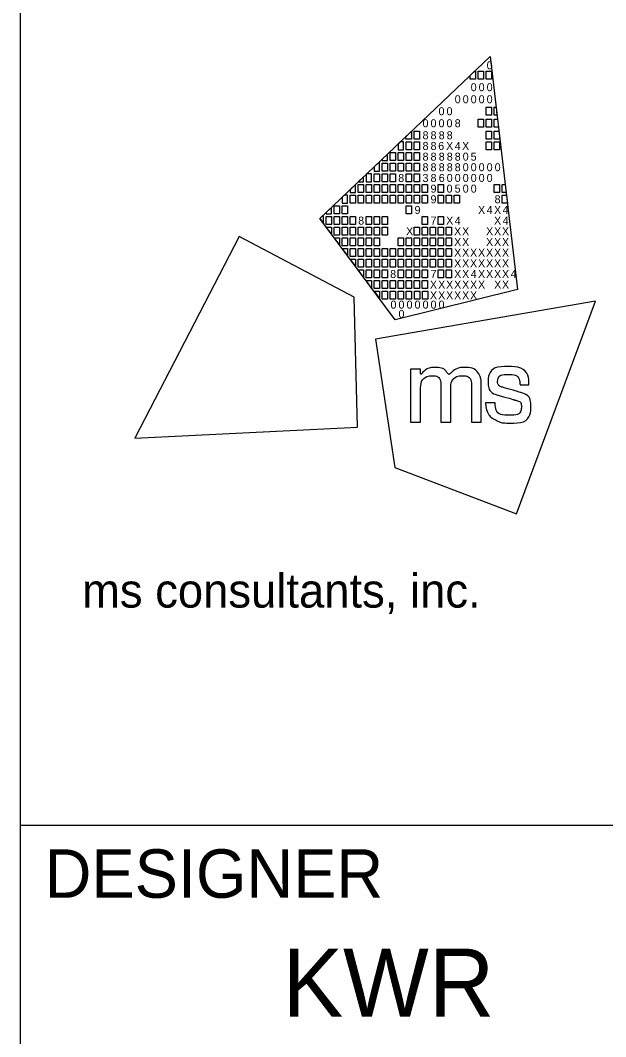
# Model space of a CAD drawing. Extents: x 0 to 34, y 0 to 22.
# Drawn here: x 32 to 33.207, y 2.063 to 4.161 of the extents above; entities that cross this region are included whole.
import ezdxf

# ---------------------------------------------------------------- set-up
doc = ezdxf.new("R2010")
doc.units = 0
doc.layers.add('SH_Border', color=7, linetype='Continuous')
doc.layers.add('SH_Data', color=7, linetype='Continuous')

msp = doc.modelspace()

# ---------------------------------------------------------------- linework, layer by layer
at = {"layer": 'SH_Border'}
for p, q in [((32, 0.5), (32, 21.5)), ((32, 2.5), (33.5, 2.5))]:
    msp.add_line(p, q, dxfattribs=at)
at = {"layer": 'SH_Data'}
for p, q in [((32.6175, 3.7519), (32.9688, 4.0861)), ((32.9688, 4.0861), (32.9688, 4.0861)), ((32.9688, 4.0861), (33.0253, 3.6052)), ((32.773, 3.543), (32.6175, 3.7519)), ((33.0253, 3.6052), (32.773, 3.543)), ((32.75, 3.5), (32.75, 3.5))]:
    msp.add_line(p, q, dxfattribs=at)
for points in [[(32.9279, 4.0472), (32.9369, 4.0558), (32.9389, 4.0558), (32.9389, 4.0393), (32.9279, 4.0393)], [(32.9444, 4.0558), (32.9554, 4.0558), (32.9554, 4.0393), (32.9444, 4.0393)], [(32.9609, 4.0558), (32.9719, 4.0558), (32.9719, 4.0393), (32.9609, 4.0393)], [(32.9606, 3.9815), (32.9716, 3.9815), (32.9716, 3.965), (32.9606, 3.965)], [(32.9771, 3.9815), (32.9811, 3.9815), (32.983, 3.965), (32.9771, 3.965)], [(32.9441, 3.9567), (32.9551, 3.9567), (32.9551, 3.9402), (32.9441, 3.9402)], [(32.9606, 3.9567), (32.9716, 3.9567), (32.9716, 3.9402), (32.9606, 3.9402)], [(32.9771, 3.9567), (32.984, 3.9567), (32.9859, 3.9402), (32.9771, 3.9402)], [(32.7953, 3.9211), (32.8064, 3.9316), (32.8064, 3.9154), (32.7953, 3.9154)], [(32.8123, 3.9319), (32.8233, 3.9319), (32.8233, 3.9154), (32.8123, 3.9154)], [(32.9606, 3.9319), (32.9716, 3.9319), (32.9716, 3.9154), (32.9606, 3.9154)], [(32.9771, 3.9319), (32.9869, 3.9319), (32.9881, 3.9218), (32.9881, 3.9154), (32.9771, 3.9154)], [(32.7958, 3.9099), (32.8068, 3.9099), (32.8068, 3.8934), (32.7958, 3.8934)], [(32.8123, 3.9099), (32.8233, 3.9099), (32.8233, 3.8934), (32.8123, 3.8934)], [(32.9606, 3.9099), (32.9716, 3.9099), (32.9716, 3.8934), (32.9606, 3.8934)], [(32.9771, 3.9099), (32.9881, 3.9099), (32.9881, 3.8934), (32.9771, 3.8934)], [(32.7627, 3.8879), (32.7737, 3.8879), (32.7737, 3.8714), (32.7627, 3.8714)], [(32.7793, 3.8879), (32.7903, 3.8879), (32.7903, 3.8714), (32.7793, 3.8714)], [(32.7958, 3.8879), (32.8068, 3.8879), (32.8068, 3.8714), (32.7958, 3.8714)], [(32.8123, 3.8879), (32.8233, 3.8879), (32.8233, 3.8714), (32.8123, 3.8714)], [(32.7462, 3.8659), (32.7572, 3.8659), (32.7572, 3.8494), (32.7462, 3.8494)], [(32.7627, 3.8659), (32.7737, 3.8659), (32.7737, 3.8494), (32.7627, 3.8494)], [(32.7793, 3.8659), (32.7903, 3.8659), (32.7903, 3.8494), (32.7793, 3.8494)], [(32.7958, 3.8659), (32.8068, 3.8659), (32.8068, 3.8494), (32.7958, 3.8494)], [(32.8123, 3.8659), (32.8233, 3.8659), (32.8233, 3.8494), (32.8123, 3.8494)], [(32.7297, 3.8439), (32.7407, 3.8439), (32.7407, 3.8273), (32.7297, 3.8273)], [(32.7462, 3.8439), (32.7572, 3.8439), (32.7572, 3.8273), (32.7462, 3.8273)], [(32.7627, 3.8439), (32.7737, 3.8439), (32.7737, 3.8273), (32.7627, 3.8273)], [(32.7958, 3.8439), (32.8068, 3.8439), (32.8068, 3.8273), (32.7958, 3.8273)], [(32.8123, 3.8439), (32.8233, 3.8439), (32.8233, 3.8273), (32.8123, 3.8273)], [(32.6967, 3.8218), (32.7077, 3.8218), (32.7077, 3.8053), (32.6967, 3.8053)], [(32.7132, 3.8218), (32.7242, 3.8218), (32.7242, 3.8053), (32.7132, 3.8053)], [(32.7297, 3.8218), (32.7407, 3.8218), (32.7407, 3.8053), (32.7297, 3.8053)], [(32.7462, 3.8218), (32.7572, 3.8218), (32.7572, 3.8053), (32.7462, 3.8053)], [(32.7627, 3.8218), (32.7737, 3.8218), (32.7737, 3.8053), (32.7627, 3.8053)], [(32.7793, 3.8218), (32.7903, 3.8218), (32.7903, 3.8053), (32.7793, 3.8053)], [(32.7958, 3.8218), (32.8068, 3.8218), (32.8068, 3.8053), (32.7958, 3.8053)], [(32.8123, 3.8218), (32.8233, 3.8218), (32.8233, 3.8053), (32.8123, 3.8053)], [(32.8288, 3.8218), (32.8398, 3.8218), (32.8398, 3.8053), (32.8288, 3.8053)], [(32.8618, 3.8218), (32.8728, 3.8218), (32.8728, 3.8053), (32.8618, 3.8053)], [(32.9771, 3.8218), (32.9881, 3.8218), (32.9881, 3.8053), (32.9771, 3.8053)], [(32.9935, 3.8218), (32.9998, 3.8218), (33.0018, 3.8053), (32.9935, 3.8053)], [(32.6802, 3.7998), (32.6912, 3.7998), (32.6912, 3.7833), (32.6802, 3.7833)], [(32.6967, 3.7998), (32.7077, 3.7998), (32.7077, 3.7833), (32.6967, 3.7833)], [(32.7132, 3.7998), (32.7242, 3.7998), (32.7242, 3.7833), (32.7132, 3.7833)], [(32.7297, 3.7998), (32.7407, 3.7998), (32.7407, 3.7833), (32.7297, 3.7833)], [(32.7462, 3.7998), (32.7572, 3.7998), (32.7572, 3.7833), (32.7462, 3.7833)], [(32.7627, 3.7998), (32.7737, 3.7998), (32.7737, 3.7833), (32.7627, 3.7833)], [(32.7793, 3.7998), (32.7903, 3.7998), (32.7903, 3.7833), (32.7793, 3.7833)], [(32.7958, 3.7998), (32.8068, 3.7998), (32.8068, 3.7833), (32.7958, 3.7833)], [(32.8123, 3.7998), (32.8233, 3.7998), (32.8233, 3.7833), (32.8123, 3.7833)], [(32.8288, 3.7998), (32.8398, 3.7998), (32.8398, 3.7833), (32.8288, 3.7833)], [(32.8618, 3.7998), (32.8728, 3.7998), (32.8728, 3.7833), (32.8618, 3.7833)], [(32.8783, 3.7998), (32.8893, 3.7998), (32.8893, 3.7833), (32.8783, 3.7833)], [(32.8947, 3.7998), (32.9057, 3.7998), (32.9057, 3.7833), (32.8947, 3.7833)], [(32.9935, 3.7998), (33.0024, 3.7998), (33.0044, 3.7833), (32.9935, 3.7833)], [(32.6471, 3.7778), (32.6581, 3.7778), (32.6581, 3.7613), (32.6471, 3.7613)], [(32.6637, 3.7778), (32.6747, 3.7778), (32.6747, 3.7613), (32.6637, 3.7613)], [(32.7958, 3.7778), (32.8068, 3.7778), (32.8068, 3.7613), (32.7958, 3.7613)], [(32.6306, 3.7558), (32.6416, 3.7558), (32.6416, 3.7393), (32.6306, 3.7393)], [(32.6471, 3.7558), (32.6581, 3.7558), (32.6581, 3.7393), (32.6471, 3.7393)], [(32.6637, 3.7558), (32.6747, 3.7558), (32.6747, 3.7393), (32.6637, 3.7393)], [(32.6802, 3.7558), (32.6912, 3.7558), (32.6912, 3.7393), (32.6802, 3.7393)], [(32.7132, 3.7558), (32.7242, 3.7558), (32.7242, 3.7393), (32.7132, 3.7393)], [(32.7297, 3.7558), (32.7407, 3.7558), (32.7407, 3.7393), (32.7297, 3.7393)], [(32.7462, 3.7558), (32.7572, 3.7558), (32.7572, 3.7393), (32.7462, 3.7393)], [(32.8288, 3.7558), (32.8398, 3.7558), (32.8398, 3.7393), (32.8288, 3.7393)], [(32.8618, 3.7558), (32.8728, 3.7558), (32.8728, 3.7393), (32.8618, 3.7393)], [(32.6306, 3.7338), (32.6416, 3.7338), (32.6416, 3.72)], [(32.6471, 3.7338), (32.6581, 3.7338), (32.6581, 3.7173), (32.6471, 3.7173)], [(32.6637, 3.7338), (32.6747, 3.7338), (32.6747, 3.7173), (32.6637, 3.7173)], [(32.6802, 3.7338), (32.6912, 3.7338), (32.6912, 3.7173), (32.6802, 3.7173)], [(32.6967, 3.7338), (32.7077, 3.7338), (32.7077, 3.7173), (32.6967, 3.7173)], [(32.7132, 3.7338), (32.7242, 3.7338), (32.7242, 3.7173), (32.7132, 3.7173)], [(32.7297, 3.7338), (32.7407, 3.7338), (32.7407, 3.7173), (32.7297, 3.7173)], [(32.7462, 3.7338), (32.7572, 3.7338), (32.7572, 3.7173), (32.7462, 3.7173)], [(32.8123, 3.7338), (32.8233, 3.7338), (32.8233, 3.7173), (32.8123, 3.7173)], [(32.8288, 3.7338), (32.8398, 3.7338), (32.8398, 3.7173), (32.8288, 3.7173)], [(32.8453, 3.7338), (32.8563, 3.7338), (32.8563, 3.7173), (32.8453, 3.7173)], [(32.8618, 3.7338), (32.8728, 3.7338), (32.8728, 3.7173), (32.8618, 3.7173)], [(32.8783, 3.7338), (32.8893, 3.7338), (32.8893, 3.7173), (32.8783, 3.7173)], [(32.6471, 3.7117), (32.6581, 3.7117), (32.6581, 3.698)], [(32.6637, 3.7117), (32.6747, 3.7117), (32.6747, 3.6952), (32.6637, 3.6952)], [(32.6802, 3.7117), (32.6912, 3.7117), (32.6912, 3.6952), (32.6802, 3.6952)], [(32.6967, 3.7117), (32.7077, 3.7117), (32.7077, 3.6952), (32.6967, 3.6952)], [(32.7132, 3.7117), (32.7242, 3.7117), (32.7242, 3.6952), (32.7132, 3.6952)], [(32.7297, 3.7117), (32.7407, 3.7117), (32.7407, 3.6952), (32.7297, 3.6952)], [(32.7793, 3.7117), (32.7903, 3.7117), (32.7903, 3.6952), (32.7793, 3.6952)], [(32.7958, 3.7117), (32.8068, 3.7117), (32.8068, 3.6952), (32.7958, 3.6952)], [(32.8123, 3.7117), (32.8233, 3.7117), (32.8233, 3.6952), (32.8123, 3.6952)], [(32.8288, 3.7117), (32.8398, 3.7117), (32.8398, 3.6952), (32.8288, 3.6952)], [(32.8453, 3.7117), (32.8563, 3.7117), (32.8563, 3.6952), (32.8453, 3.6952)], [(32.8618, 3.7117), (32.8728, 3.7117), (32.8728, 3.6952), (32.8618, 3.6952)], [(32.8783, 3.7117), (32.8893, 3.7117), (32.8893, 3.6952), (32.8783, 3.6952)], [(32.6637, 3.6897), (32.6747, 3.6897), (32.6747, 3.676)], [(32.6747, 3.6897), (32.6747, 3.6897), (32.6747, 3.6897)], [(32.6802, 3.6897), (32.6912, 3.6897), (32.6912, 3.6732), (32.6802, 3.6732)], [(32.6967, 3.6897), (32.7077, 3.6897), (32.7077, 3.6732), (32.6967, 3.6732)], [(32.7132, 3.6897), (32.7242, 3.6897), (32.7242, 3.6732), (32.7132, 3.6732)], [(32.7297, 3.6897), (32.7407, 3.6897), (32.7407, 3.6732), (32.7297, 3.6732)], [(32.7462, 3.6897), (32.7572, 3.6897), (32.7572, 3.6732), (32.7462, 3.6732)], [(32.7627, 3.6897), (32.7737, 3.6897), (32.7737, 3.6732), (32.7627, 3.6732)], [(32.7793, 3.6897), (32.7903, 3.6897), (32.7903, 3.6732), (32.7793, 3.6732)], [(32.7958, 3.6897), (32.8068, 3.6897), (32.8068, 3.6732), (32.7958, 3.6732)], [(32.8123, 3.6897), (32.8233, 3.6897), (32.8233, 3.6732), (32.8123, 3.6732)], [(32.8288, 3.6897), (32.8398, 3.6897), (32.8398, 3.6732), (32.8288, 3.6732)], [(32.8453, 3.6897), (32.8563, 3.6897), (32.8563, 3.6732), (32.8453, 3.6732)], [(32.8618, 3.6897), (32.8728, 3.6897), (32.8728, 3.6732), (32.8618, 3.6732)], [(32.8783, 3.6897), (32.8893, 3.6897), (32.8893, 3.6732), (32.8783, 3.6732)], [(32.6802, 3.6677), (32.6912, 3.6677), (32.6912, 3.654)], [(32.6967, 3.6677), (32.7077, 3.6677), (32.7077, 3.6512), (32.6967, 3.6512)], [(32.7132, 3.6677), (32.7242, 3.6677), (32.7242, 3.6512), (32.7132, 3.6512)], [(32.7297, 3.6677), (32.7407, 3.6677), (32.7407, 3.6512), (32.7297, 3.6512)], [(32.7462, 3.6677), (32.7572, 3.6677), (32.7572, 3.6512), (32.7462, 3.6512)], [(32.7627, 3.6677), (32.7737, 3.6677), (32.7737, 3.6512), (32.7627, 3.6512)], [(32.7793, 3.6677), (32.7903, 3.6677), (32.7903, 3.6512), (32.7793, 3.6512)], [(32.7958, 3.6677), (32.8068, 3.6677), (32.8068, 3.6512), (32.7958, 3.6512)], [(32.8123, 3.6677), (32.8233, 3.6677), (32.8233, 3.6512), (32.8123, 3.6512)], [(32.8288, 3.6677), (32.8398, 3.6677), (32.8398, 3.6512), (32.8288, 3.6512)], [(32.8453, 3.6677), (32.8563, 3.6677), (32.8563, 3.6512), (32.8453, 3.6512)], [(32.8618, 3.6677), (32.8728, 3.6677), (32.8728, 3.6512), (32.8618, 3.6512)], [(32.8783, 3.6677), (32.8893, 3.6677), (32.8893, 3.6512), (32.8783, 3.6512)], [(32.7077, 3.6305), (32.6965, 3.6457), (32.7077, 3.6457)], [(32.7132, 3.6457), (32.7242, 3.6457), (32.7242, 3.6292), (32.7132, 3.6292)], [(32.7297, 3.6457), (32.7407, 3.6457), (32.7407, 3.6292), (32.7297, 3.6292)], [(32.7462, 3.6457), (32.7572, 3.6457), (32.7572, 3.6292), (32.7462, 3.6292)], [(32.7793, 3.6457), (32.7903, 3.6457), (32.7903, 3.6292), (32.7793, 3.6292)], [(32.7958, 3.6457), (32.8068, 3.6457), (32.8068, 3.6292), (32.7958, 3.6292)], [(32.8123, 3.6457), (32.8233, 3.6457), (32.8233, 3.6292), (32.8123, 3.6292)], [(32.8288, 3.6457), (32.8398, 3.6457), (32.8398, 3.6292), (32.8288, 3.6292)], [(32.8618, 3.6457), (32.8728, 3.6457), (32.8728, 3.6292), (32.8618, 3.6292)], [(32.8783, 3.6457), (32.8893, 3.6457), (32.8893, 3.6292), (32.8783, 3.6292)], [(32.724, 3.6082), (32.7132, 3.6237), (32.7242, 3.6237)], [(32.7297, 3.6237), (32.7407, 3.6237), (32.7407, 3.6072), (32.7297, 3.6072)], [(32.7462, 3.6237), (32.7572, 3.6237), (32.7572, 3.6072), (32.7462, 3.6072)], [(32.7627, 3.6237), (32.7737, 3.6237), (32.7737, 3.6072), (32.7627, 3.6072)], [(32.7793, 3.6237), (32.7903, 3.6237), (32.7903, 3.6072), (32.7793, 3.6072)], [(32.7958, 3.6237), (32.8068, 3.6237), (32.8068, 3.6072), (32.7958, 3.6072)], [(32.8123, 3.6237), (32.8233, 3.6237), (32.8233, 3.6072), (32.8123, 3.6072)], [(32.8288, 3.6237), (32.8398, 3.6237), (32.8398, 3.6072), (32.8288, 3.6072)], [(32.7302, 3.6017), (32.7407, 3.6017), (32.7408, 3.5875)], [(32.7463, 3.6017), (32.7573, 3.6017), (32.7573, 3.5852), (32.7463, 3.5852)], [(32.763, 3.6017), (32.774, 3.6017), (32.774, 3.5852), (32.763, 3.5852)], [(32.7794, 3.6017), (32.7904, 3.6017), (32.7904, 3.5852), (32.7794, 3.5852)], [(32.796, 3.6017), (32.807, 3.6017), (32.807, 3.5852), (32.796, 3.5852)], [(32.8129, 3.6017), (32.8239, 3.6017), (32.8239, 3.5851), (32.8129, 3.5851)], [(32.8296, 3.6017), (32.8406, 3.6017), (32.8406, 3.5851), (32.8296, 3.5851)]]:
    msp.add_lwpolyline(points, close=True, dxfattribs=at)
for points in [[(32.7903, 3.9099), (32.7836, 3.9099), (32.7793, 3.9058), (32.7793, 3.8934), (32.7903, 3.8934), (32.7903, 3.9099)], [(32.7572, 3.8849), (32.7462, 3.8744), (32.7462, 3.8714), (32.7572, 3.8714), (32.7572, 3.8849)], [(32.7407, 3.8691), (32.7297, 3.8587), (32.7297, 3.8494), (32.7407, 3.8494), (32.7407, 3.8691)], [(32.7242, 3.8439), (32.7141, 3.8439), (32.7132, 3.843), (32.7132, 3.8273), (32.7242, 3.8273), (32.7242, 3.8439)], [(32.6912, 3.822), (32.6802, 3.8115), (32.6802, 3.8053), (32.6912, 3.8053), (32.6912, 3.822)], [(32.7077, 3.8377), (32.6968, 3.8273), (32.7077, 3.8273), (32.7077, 3.8377)], [(32.6747, 3.7998), (32.6679, 3.7998), (32.6637, 3.7958), (32.6637, 3.7833), (32.6747, 3.7833), (32.6747, 3.7998)], [(32.6251, 3.7558), (32.6216, 3.7558), (32.6175, 3.7519), (32.6251, 3.7417), (32.6251, 3.7558)], [(32.6416, 3.7749), (32.6306, 3.7644), (32.6306, 3.7613), (32.6416, 3.7613), (32.6416, 3.7749)], [(32.4512, 3.7149), (32.2359, 3.2988), (32.6956, 3.3215), (32.6884, 3.5892), (32.4512, 3.7149)], [(33.0229, 3.1422), (33.1859, 3.5814), (32.7324, 3.5029), (32.7722, 3.2381), (33.0229, 3.1422)]]:
    msp.add_lwpolyline(points, dxfattribs=at)
for points in [[(32.8048, 3.3315), (32.8048, 3.3315), (32.8048, 3.4409), (32.8048, 3.4409), (32.8048, 3.4409), (32.8255, 3.4409), (32.8255, 3.4409), (32.8255, 3.4409), (32.8255, 3.4297), (32.8255, 3.4297), (32.8346, 3.4399), (32.8457, 3.4445), (32.8555, 3.4445), (32.8688, 3.4445), (32.8791, 3.4372), (32.8837, 3.4266), (32.8915, 3.4381), (32.905, 3.4446), (32.9166, 3.4446), (32.9325, 3.4446), (32.9451, 3.435), (32.9494, 3.4213), (32.9494, 3.4212), (32.9494, 3.4212), (32.9494, 3.4212), (32.9501, 3.419), (32.9506, 3.4172), (32.9506, 3.4071), (32.9506, 3.4071), (32.9506, 3.3314), (32.9506, 3.3314), (32.9506, 3.3314), (32.9303, 3.3314), (32.9303, 3.3314), (32.9303, 3.3314), (32.9303, 3.4048), (32.9303, 3.4048), (32.9303, 3.4201), (32.9219, 3.4274), (32.911, 3.4274), (32.8995, 3.4274), (32.8879, 3.4171), (32.8879, 3.4001), (32.8879, 3.4001), (32.8879, 3.3315), (32.8879, 3.3315), (32.8879, 3.3315), (32.8674, 3.3315), (32.8674, 3.3315), (32.8674, 3.3315), (32.8674, 3.4059), (32.8674, 3.4059), (32.8674, 3.4203), (32.8588, 3.4274), (32.8496, 3.4274), (32.8384, 3.4274), (32.8254, 3.417), (32.8254, 3.3962), (32.8254, 3.3962), (32.8254, 3.3315), (32.8254, 3.3315), (32.8254, 3.3315), (32.8048, 3.3315), (32.8048, 3.3315)], [(32.9595, 3.3709), (32.9595, 3.3709), (32.9595, 3.3717), (32.9595, 3.3717), (32.9595, 3.3717), (32.9603, 3.3717), (32.9603, 3.3717), (32.9603, 3.3717), (32.9783, 3.3717), (32.9783, 3.3717), (32.9783, 3.3717), (32.9789, 3.3717), (32.9789, 3.3717), (32.9789, 3.3717), (32.979, 3.371), (32.979, 3.371), (32.9803, 3.3554), (32.9887, 3.346), (33.009, 3.346), (33.0273, 3.346), (33.0333, 3.3554), (33.0333, 3.3631), (33.0333, 3.3732), (33.0256, 3.3758), (33.0175, 3.378), (33.0175, 3.378), (32.987, 3.3867), (32.987, 3.3867), (32.972, 3.3909), (32.9648, 3.4019), (32.9648, 3.4142), (32.9648, 3.4303), (32.9768, 3.4462), (33.0052, 3.4462), (33.0348, 3.4462), (33.0489, 3.4285), (33.0489, 3.4095), (33.0489, 3.4095), (33.0489, 3.4087), (33.0489, 3.4087), (33.0489, 3.4087), (33.0482, 3.4087), (33.0482, 3.4087), (33.0482, 3.4087), (33.0312, 3.4087), (33.0312, 3.4087), (33.0312, 3.4087), (33.0305, 3.4087), (33.0305, 3.4087), (33.0305, 3.4087), (33.0305, 3.4094), (33.0305, 3.4094), (33.0301, 3.4208), (33.0226, 3.43), (33.0056, 3.43), (32.9891, 3.43), (32.9843, 3.4218), (32.9843, 3.4157), (32.9843, 3.4108), (32.9869, 3.4059), (32.9959, 3.4033), (32.9959, 3.4033), (33.0255, 3.3948), (33.0255, 3.3948), (33.0462, 3.3889), (33.0527, 3.3777), (33.0527, 3.3639), (33.0527, 3.3462), (33.041, 3.3298), (33.0087, 3.3298), (32.9952, 3.3298), (32.9877, 3.3321), (32.9823, 3.3348), (32.969, 3.3414), (32.9609, 3.3536), (32.9595, 3.3709)]]:
    msp.add_open_spline(points, degree=3, dxfattribs=at)

# ---------------------------------------------------------------- texts
for s, height, p in [('0', 0.0165, (32.9617, 4.0597)), ('0', 0.0165, (32.9288, 4.0145)), ('0', 0.0165, (32.9452, 4.0145)), ('0', 0.0165, (32.9617, 4.0145)), ('0', 0.0165, (32.8958, 3.9897)), ('0', 0.0165, (32.9123, 3.9897)), ('0', 0.0165, (32.9288, 3.9897)), ('0', 0.0165, (32.9452, 3.9897)), ('0', 0.0165, (32.9617, 3.9897)), ('0', 0.0165, (32.8625, 3.965)), ('0', 0.0165, (32.879, 3.965)), ('0', 0.0165, (32.8295, 3.9402)), ('0', 0.0165, (32.846, 3.9402)), ('0', 0.0165, (32.8625, 3.9402)), ('0', 0.0165, (32.879, 3.9402)), ('8', 0.0165, (32.8958, 3.9402)), ('8', 0.0165, (32.8295, 3.9154)), ('8', 0.0165, (32.846, 3.9154)), ('8', 0.0165, (32.8628, 3.9154)), ('8', 0.0165, (32.8793, 3.9154)), ('8', 0.0165, (32.8295, 3.8934)), ('8', 0.0165, (32.846, 3.8934)), ('6', 0.0165, (32.8618, 3.8934)), ('X', 0.0165, (32.8781, 3.8934)), ('4', 0.0165, (32.8958, 3.8934)), ('X', 0.0165, (32.911, 3.8934)), ('8', 0.0165, (32.8295, 3.8713)), ('8', 0.0165, (32.846, 3.8713)), ('8', 0.0165, (32.8628, 3.8713)), ('8', 0.0165, (32.8794, 3.8713)), ('8', 0.0165, (32.8958, 3.8713)), ('0', 0.0165, (32.9123, 3.8713)), ('5', 0.0165, (32.9287, 3.8713)), ('8', 0.0165, (32.8295, 3.8494)), ('8', 0.0165, (32.846, 3.8494)), ('8', 0.0165, (32.8628, 3.8494)), ('8', 0.0165, (32.8794, 3.8494)), ('8', 0.0165, (32.8958, 3.8494)), ('0', 0.0165, (32.9123, 3.8494)), ('0', 0.0165, (32.9288, 3.8494)), ('0', 0.0165, (32.9452, 3.8494)), ('0', 0.0165, (32.9617, 3.8494)), ('0', 0.0165, (32.9782, 3.8494)), ('8', 0.0165, (32.7793, 3.8273)), ('3', 0.0165, (32.8295, 3.8273)), ('8', 0.0165, (32.846, 3.8273)), ('6', 0.0165, (32.8629, 3.8273)), ('0', 0.0165, (32.8793, 3.8273)), ('0', 0.0165, (32.8958, 3.8273)), ('0', 0.0165, (32.9123, 3.8273)), ('0', 0.0165, (32.9288, 3.8273)), ('0', 0.0165, (32.9452, 3.8273)), ('0', 0.0165, (32.9617, 3.8273)), ('9', 0.0165, (32.846, 3.8053)), ('0', 0.0165, (32.879, 3.8053)), ('5', 0.0165, (32.8957, 3.8053)), ('0', 0.0165, (32.9123, 3.8053)), ('0', 0.0165, (32.9288, 3.8053)), ('9', 0.0165, (32.846, 3.7833)), ('8', 0.0165, (32.9781, 3.7833)), ('9', 0.0165, (32.813, 3.7613)), ('X', 0.0165, (32.9439, 3.7613)), ('4', 0.0165, (32.9617, 3.7613)), ('X', 0.0165, (32.9769, 3.7613)), ('4', 0.0165, (32.9946, 3.7613)), ('8', 0.0165, (32.6967, 3.7393)), ('7', 0.0165, (32.846, 3.7393)), ('X', 0.0165, (32.8781, 3.7393)), ('4', 0.0165, (32.8958, 3.7393)), ('X', 0.0165, (32.9769, 3.7393)), ('4', 0.0165, (32.9946, 3.7393)), ('X', 0.0165, (32.7955, 3.7173)), ('X', 0.0165, (32.8945, 3.7173)), ('X', 0.0165, (32.911, 3.7173)), ('X', 0.0165, (32.9604, 3.7173)), ('X', 0.0165, (32.9769, 3.7173)), ('X', 0.0165, (32.9933, 3.7173)), ('X', 0.0165, (32.8945, 3.6952)), ('X', 0.0165, (32.911, 3.6952)), ('X', 0.0165, (32.9604, 3.6952)), ('X', 0.0165, (32.9769, 3.6952)), ('X', 0.0165, (32.9933, 3.6952)), ('X', 0.0165, (32.8945, 3.6732)), ('X', 0.0165, (32.911, 3.6732)), ('X', 0.0165, (32.9274, 3.6732)), ('X', 0.0165, (32.9439, 3.6732)), ('X', 0.0165, (32.9604, 3.6732)), ('X', 0.0165, (32.9769, 3.6732)), ('X', 0.0165, (32.9933, 3.6732)), ('X', 0.0165, (32.8945, 3.6512)), ('X', 0.0165, (32.911, 3.6512)), ('X', 0.0165, (32.9274, 3.6512)), ('X', 0.0165, (32.9439, 3.6512)), ('X', 0.0165, (32.9604, 3.6512)), ('X', 0.0165, (32.9769, 3.6512)), ('X', 0.0165, (32.9933, 3.6512)), ('8', 0.0165, (32.7627, 3.6292)), ('7', 0.0165, (32.846, 3.6292)), ('X', 0.0165, (32.8945, 3.6292)), ('X', 0.0165, (32.911, 3.6292)), ('4', 0.0165, (32.9288, 3.6292)), ('X', 0.0165, (32.9439, 3.6292)), ('X', 0.0165, (32.9604, 3.6292)), ('X', 0.0165, (32.9769, 3.6292)), ('X', 0.0165, (32.9933, 3.6292)), ('4', 0.0165, (33.0111, 3.6292)), ('X', 0.0165, (32.8447, 3.6072)), ('X', 0.0165, (32.8616, 3.6072)), ('X', 0.0165, (32.878, 3.6072)), ('X', 0.0165, (32.8945, 3.6072)), ('X', 0.0165, (32.911, 3.6072)), ('X', 0.0165, (32.9274, 3.6072)), ('X', 0.0165, (32.9439, 3.6072)), ('X', 0.0165, (32.9771, 3.6072)), ('X', 0.0165, (32.9933, 3.6072)), ('X', 0.0165, (32.8447, 3.5851)), ('X', 0.0165, (32.8616, 3.5851)), ('X', 0.0165, (32.878, 3.5851)), ('X', 0.0165, (32.8945, 3.5851)), ('X', 0.0165, (32.911, 3.5851)), ('X', 0.0165, (32.9274, 3.5851)), ('0', 0.0165, (32.7634, 3.5659)), ('0', 0.0165, (32.7799, 3.5659)), ('0', 0.0165, (32.7965, 3.5659)), ('0', 0.0165, (32.813, 3.5659)), ('0', 0.0165, (32.8295, 3.5659)), ('0', 0.0165, (32.846, 3.5659)), ('0', 0.0165, (32.8625, 3.5659)), ('0', 0.0165, (32.7799, 3.5467)), ('ms consultants, inc.', 0.07, (32.1273, 2.9489))]:
    msp.add_text(s, height=height, rotation=360, dxfattribs=at).set_placement(p)
for s, height, p in [('DESIGNER', 0.1, (32.05, 2.35)), ('KWR', 0.14, (32.5407, 2.105))]:
    msp.add_text(s, height=height, dxfattribs=at).set_placement(p)

doc.saveas('drawing.dxf')
